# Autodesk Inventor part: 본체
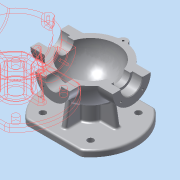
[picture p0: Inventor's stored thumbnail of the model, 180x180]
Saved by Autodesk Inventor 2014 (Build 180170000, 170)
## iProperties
Created: 2015-12
Part Number: 본체
Material: 알루미늄 6061
Document SubType Name: Modeling
Designer: mduedu
Density: 2.71 g/cm^3
Appearance: 알루미늄 - 평지
Mass: 1035.31 g
Surface Area: 843.851 cm^2
Volume: 382.033 cm^3
Author: mduedu
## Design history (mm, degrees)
sketch "스케치1"
  geometry: L1 (-53, 0)-(53, 0); A1 r 53 centre (0, 0) between (53, 0) and (-53, 0); 2 further points
  constraints: 2 coincident, 2 end point, 2 point on circle, 1 centre point, 1 horizontal, 1 midpoint
  dimensions: "d0" = 53 radius of A1
revolve "회전1" sketch "스케치1" stored, may be unused: angle "d2" = 90 deg
feature "쉘1" dims "d11" = 10
node "작업 평면1"
sketch "스케치2"
  geometry: C1 r 31 at (0, 0); 1 further point
  constraints: 1 centre point, 1 coincident
  dimensions: "d4" = 62 diameter of C1
extrude "돌출1" join sketch "스케치2" stored distance "d5" = 10; taper "d6" = 0 deg
node "작업 평면2"
sketch "스케치3"
  geometry: C1 r 28 at (0, 0); 1 further point
  constraints: 1 centre point, 1 coincident
  dimensions: "d8" = 56 diameter of C1
extrude "돌출2" join sketch "스케치3" stored distance "d9" = 10; taper "d10" = 0 deg
hole "구멍1" diameter "d14" = 35; stored, may be unused: countersink angle "d18" = 90 deg, drill point angle "d20" = 0 deg; dims "d12" = 10, "d13" = 10, "d15" = 6, "d16" = 4, "d17" = 2, "d19" = 16
hole "구멍2" diameter "d23" = 27; stored, may be unused: countersink angle "d27" = 90 deg, drill point angle "d29" = 0 deg; dims "d21" = 10, "d22" = 10, "d24" = 6, "d25" = 4, "d26" = 2, "d28" = 16
fillet "모깎기1" dims "d30" = 0.3
hole "구멍3" diameter "d33" = 26; stored, may be unused: countersink angle "d37" = 90 deg, drill point angle "d39" = 0 deg; dims "d31" = 10, "d32" = 10, "d34" = 6, "d35" = 4, "d36" = 2, "d38" = 16
chamfer "모따기1" distance "d40" = 1; stored, may be unused: second distance "d41" = 2, angle "d42" = 45 deg
sketch "스케치4"
  geometry: L1 (0, 0)-(0, -25); L2 (0, 0)-(-17.678, -17.678); A1 r 25 centre (0, 0) between (-17.678, -17.678) and (0, -25); 1 further point
  constraints: 4 end point, 2 point on circle, 1 centre point, 1 coincident, 1 vertical
  dimensions: "d43" = 50 diameter of A1; "d47" = 45 deg angle of L1 L2
hole "구멍4" sketch "스케치4" at (-17.678, -17.678) diameter "d49" = 3.242; stored, may be unused: countersink angle "d53" = 90 deg, drill point angle "d55" = 118 deg; dims "d50" = 11, "d51" = 4, "d52" = 2, "d54" = 13
sketch "스케치5"
  geometry: L1 (0, 0)-(0, -20); L2 (0, 0)-(-14.142, -14.142); A1 r 20 centre (0, 0) between (0, -20) and (-14.142, -14.142); 2 further points
  constraints: 4 end point, 2 coincident, 2 point on circle, 1 centre point, 1 vertical
  dimensions: "d59" = 40 diameter of A1; "d65" = 45 deg angle of L1 L2
hole "구멍5" sketch "스케치5" at (-14.142, -14.142) diameter "d67" = 3.242; stored, may be unused: countersink angle "d71" = 90 deg, drill point angle "d73" = 118 deg; dims "d68" = 8, "d69" = 4, "d70" = 2, "d72" = 10
node "작업 평면3"
sketch "스케치6"
  geometry: C1 r 75 at (0, 0); 1 further point
  constraints: 1 centre point, 1 coincident
  dimensions: "d78" = 150 diameter of C1
extrude "돌출3" join sketch "스케치6" distance "d80" = 10; taper "d81" = 0 deg
sketch "스케치7"
  geometry: C1 r 20 at (0, 0); 1 further point
  constraints: 1 centre point, 1 coincident
  dimensions: "d82" = 40 diameter of C1
extrude "돌출4" join sketch "스케치7" stored distance "d84" = 10; taper "d85" = 0 deg
sketch "스케치8"
  geometry: 2 further points
  constraints: 1 coincident
hole "구멍6" sketch "스케치8" at (0, 0) diameter "d86" = 20; stored, may be unused: countersink angle "d90" = 90 deg, drill point angle "d92" = 118 deg; dims "d87" = 7, "d88" = 40, "d89" = 5, "d91" = 10
fillet "모깎기2" dims "d93" = 0.3
sketch "스케치9"
  geometry: L1 (75, -75)-(-75, -75) reference; L2 (-45, -75)-(-38.245, -36.692); A1 r 53 centre (0, 0) between (42.988, 31) and (42.988, -31) reference; 1 further point
  constraints: 2 end point, 1 point on circle, 1 point on line
  dimensions: "d94" = 45 horizontal distance of L2.start point (0, 0); "d95" = 80 deg angle of L2 L1
feature "리브1" sketch "스케치9" dims "d96" = 1, "d97" = 8, "d98" = 0, "d99" = 0, "d100" = 1, "d101" = 1
sketch "스케치14"
  geometry: L1 (-45, 110)-(45, 110); L2 (45, 110)-(45, 60); L3 (45, 60)-(-45, 60); L4 (-45, 60)-(-45, 110); L5 (-45, 110)-(45, 60); L6 (45, 110)-(-45, 60); L7 (-75, 0)-(75, 0); L8 (-45, -110)-(45, -110); L9 (45, -110)-(45, -60); L10 (45, -60)-(-45, -60); L11 (-45, -60)-(-45, -110); L12 (-45, -110)-(45, -60); L13 (45, -110)-(-45, -60); A1 r 75 centre (0, 0) between (45, 60) and (-45, 60) reference; 4 further points
  constraints: 26 end point, 5 midpoint, 5 symmetric about line, 4 point on circle, 2 parallel, 2 perpendicular, 1 coincident, 1 horizontal
  dimensions: "d151" = 15 distance edge to line of A1 L3; "d152" = 50 distance of L3.end L1.start
extrude "돌출7" cut sketch "스케치14" stored distance "d153" = 0; taper "d154" = 0 deg
fillet "모깎기9" dims "d155" = 10
sketch "스케치10"
  geometry: L1 (0, 0)-(0, -55); L2 (0, 0)-(-38.891, -38.891); A1 r 55 centre (0, 0) between (0, -55) and (-38.891, -38.891); 2 further points
  constraints: 4 end point, 2 coincident, 2 point on circle, 1 centre point, 1 vertical
  dimensions: "d105" = 110 diameter of A1; "d107" = 45 deg angle of L1 L2
hole "구멍7" sketch "스케치10" at (-38.891, -38.891) diameter "d109" = 10; stored, may be unused: countersink angle "d113" = 90 deg, drill point angle "d115" = 118 deg; dims "d110" = 7, "d111" = 40, "d112" = 5, "d114" = 10
fillet "모깎기3" dims "d120" = 3
fillet "모깎기4" dims "d121" = 3, "d122" = 3
fillet "모깎기5" dims "d123" = 3
fillet "모깎기6" dims "d124" = 3
sketch "스케치11"
  geometry: 2 further points
  constraints: 1 vertical alignment, 1 other
  dimensions: "d157" = 63 distance of point (0, 63) point (0, 0)
feature "엠보싱1" sketch "스케치11" dims "d125" = 0.5, "d126" = 0
sketch "스케치12"
  geometry: L1 (0, 100)-(0, -100); L2 (0, 100)-(100, 100); L3 (100, 100)-(100, -100); L4 (100, -100)-(0, -100); 2 further points
  constraints: 8 end point, 3 perpendicular, 1 coincident, 1 midpoint, 1 vertical
  dimensions: "d127" = 200 distance of L2.end L3.end; "d129" = 100 distance between parallel lines of L1 L3
extrude "돌출5" cut sketch "스케치12" stored distance "d130" = 10; taper "d131" = 0 deg
sketch "스케치13"
  geometry: C1 r 7 at (0, 53); A1 r 53 centre (0, 0) between (42.113, 32.179) and (-42.113, 32.179) reference; 1 further point
  constraints: 1 centre point, 1 point on circle
  dimensions: "d132" = 14 diameter of C1
extrude "돌출6" join sketch "스케치13" distance "d134" = 15; taper "d135" = 0 deg; dims "d29" = 0
hole "구멍8" diameter "d139" = 3.242; stored, may be unused: countersink angle "d143" = 90 deg, drill point angle "d145" = 118 deg; dims "d140" = 8, "d141" = 4, "d142" = 2, "d144" = 10, "d148" = 10, "d149" = 10
fillet "모깎기7" dims "d146" = 3
fillet "모깎기8" dims "d147" = 3
node "솔리드1"
mirror "대칭1"
mirror "대칭2"
pattern_circular "원형 패턴1" dims angle "d57" = 360 deg
mirror "대칭3"
pattern_circular "원형 패턴2" dims angle "d75" = 360 deg
pattern_circular "원형 패턴3" dims angle "d103" = 360 deg
pattern_circular "원형 패턴4" dims angle "d118" = 360 deg
other parameters: "d3" = 67, "d7" = 62, "d77" = -85
